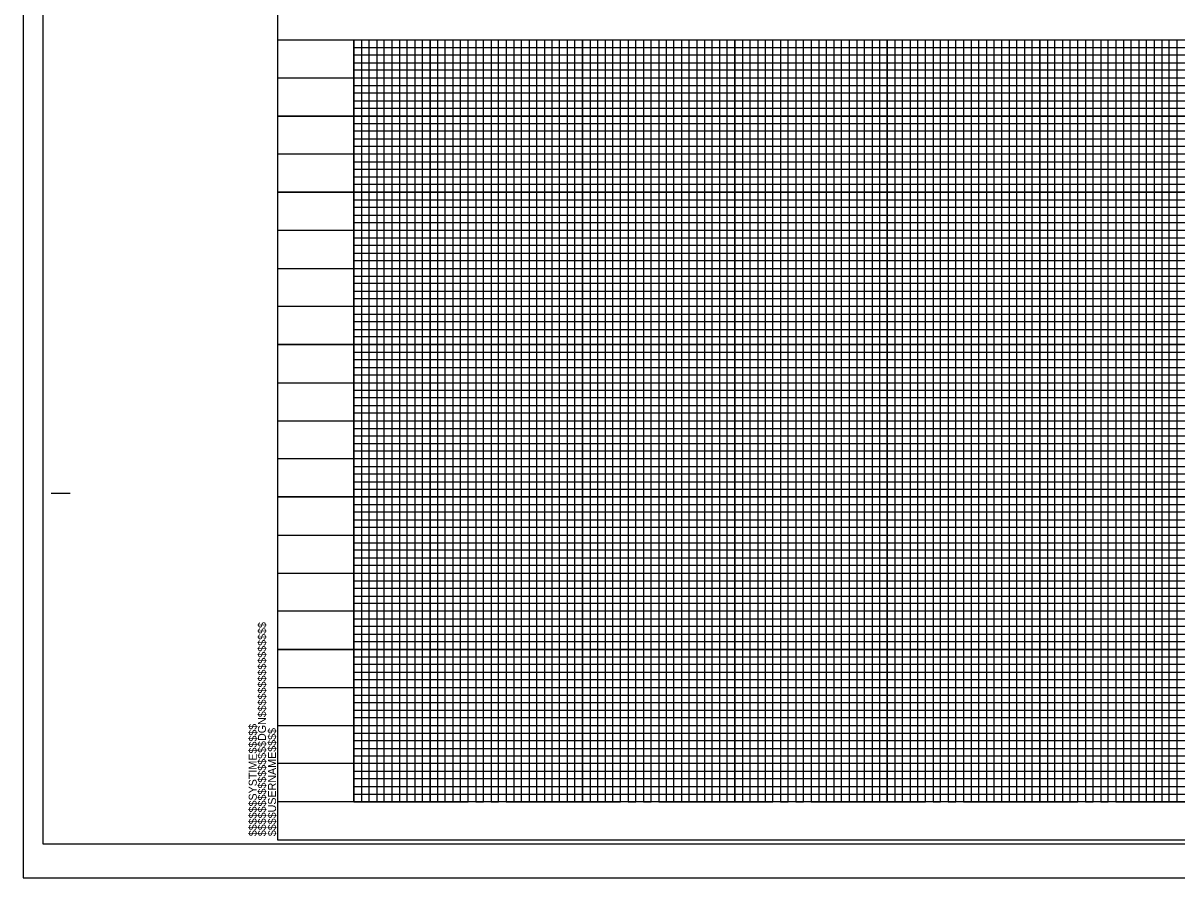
# Model space of a CAD drawing. Extents: x 1648435 to 1651603, y 802691 to 845762.
# Drawn here: x 1648862 to 1649619, y 802691 to 803252 of the extents above; entities that cross this region are included whole.
import ezdxf

# ---------------------------------------------------------------- set-up
doc = ezdxf.new("R2010")
doc.units = 0
for name, color, linetype in [('Sheet Cutting Line CELL', 7, 'Continuous'), ('Sheet DOT Grid CELL', 7, 'Continuous'), ('Sheet Layout Profile Border Port 2', 7, 'Continuous'), ('Sheet Plot Border Inside CELL', 7, 'Continuous'), ('Sheet Plot Border Outside CELL', 7, 'Continuous'), ('Sheet Profile CELL', 7, 'Continuous'), ('Sheet Profile Grid Major CELL', 7, 'Continuous'), ('Sheet Profile Grid Middle CELL', 7, 'Continuous'), ('Sheet Profile Grid Minor CELL', 7, 'Continuous')]:
    doc.layers.add(name, color=color, linetype=linetype)

msp = doc.modelspace()

# ---------------------------------------------------------------- linework, layer by layer
at = {"layer": 'Sheet Cutting Line CELL'}
for p, q in [((1648862.28, 803791.02), (1648862.28, 802691.02)), ((1648862.28, 802691.02), (1650546.28, 802691.02))]:
    msp.add_line(p, q, dxfattribs=at)
at = {"layer": 'Sheet DOT Grid CELL'}
for p, q in [((1649029.28, 803241.02), (1650529.17, 803241.02)), ((1649079.28, 803241.02), (1649079.28, 802741.02)), ((1649129.28, 803241.02), (1649129.28, 802741.02)), ((1649179.28, 803241.02), (1649179.28, 802741.02)), ((1649229.28, 803241.02), (1649229.28, 802741.02)), ((1649279.28, 803241.02), (1649279.28, 802741.02)), ((1649329.28, 803241.02), (1649329.28, 802741.02)), ((1649379.28, 803241.02), (1649379.28, 802741.02)), ((1649429.28, 803241.02), (1649429.28, 802741.02)), ((1649479.28, 803241.02), (1649479.28, 802741.02)), ((1649529.28, 803241.02), (1649529.28, 802741.02)), ((1649579.28, 803241.02), (1649579.28, 802741.02)), ((1649029.28, 803191.02), (1650529.17, 803191.02)), ((1649029.28, 803141.02), (1650529.17, 803141.02)), ((1649029.28, 803091.02), (1650529.17, 803091.02)), ((1649029.28, 803041.02), (1650529.17, 803041.02)), ((1649029.28, 802991.02), (1650529.17, 802991.02)), ((1649029.28, 802941.02), (1650529.17, 802941.02)), ((1649029.28, 802891.02), (1650529.17, 802891.02)), ((1649029.28, 802841.02), (1650529.17, 802841.02)), ((1649029.28, 802791.02), (1650529.17, 802791.02))]:
    msp.add_line(p, q, dxfattribs=at)
at = {"layer": 'Sheet Layout Profile Border Port 2'}
msp.add_lwpolyline([(1649079.28, 803241.02), (1650479.28, 803241.02), (1650479.28, 802741.02), (1649079.28, 802741.02)], close=True, dxfattribs=at)
at = {"layer": 'Sheet Plot Border Inside CELL'}
msp.add_lwpolyline([(1648875.28, 802713.47), (1650541.78, 802713.47), (1650541.78, 803768.57), (1648875.28, 803768.57)], close=True, dxfattribs=at)
at = {"layer": 'Sheet Plot Border Outside CELL'}
msp.add_lwpolyline([(1648862.28, 802691.02), (1650546.28, 802691.02), (1650546.28, 803791.02), (1648862.28, 803791.02)], close=True, dxfattribs=at)
at = {"layer": 'Sheet Profile CELL'}
for p, q in [((1649029.28, 803241.02), (1650529.28, 803241.02)), ((1648880.78, 802943.52), (1648893.28, 802943.52)), ((1650529.28, 802741.02), (1649029.28, 802741.02)), ((1649029.28, 802716.02), (1650529.28, 802716.02)), ((1649029.28, 802716.02), (1649029.28, 802716.02)), ((1649029.28, 802716.02), (1649029.28, 802716.02)), ((1649029.28, 802716.02), (1649029.28, 802716.02)), ((1649029.28, 802716.02), (1649029.28, 802716.02)), ((1649029.28, 802716.02), (1649029.28, 802716.02)), ((1649029.28, 802716.02), (1649029.28, 802716.02)), ((1649029.28, 802716.02), (1649029.28, 802716.02))]:
    msp.add_line(p, q, dxfattribs=at)
msp.add_lwpolyline([(1650529.28, 803766.02), (1649029.28, 803766.02), (1649029.28, 802716.02), (1650529.28, 802716.02)], close=True, dxfattribs=at)
msp.add_lwpolyline([(1649066.78, 802716.02), (1649066.78, 802716.02)], dxfattribs=at)
at = {"layer": 'Sheet Profile Grid Major CELL'}
for p, q in [((1649529.28, 803241.02), (1649579.28, 803241.02)), ((1649029.28, 802741.02), (1649029.28, 802741.02))]:
    msp.add_line(p, q, dxfattribs=at)
for points in [[(1649079.28, 803241.02), (1649079.28, 802741.02), (1649129.28, 802741.02), (1649129.28, 803241.02), (1649179.28, 803241.02), (1649179.28, 802741.02), (1649229.28, 802741.02), (1649229.28, 803241.02), (1649279.28, 803241.02), (1649279.28, 802741.02), (1649329.28, 802741.02), (1649329.28, 803241.02), (1649379.28, 803241.02), (1649379.28, 802741.02), (1649429.28, 802741.02), (1649429.28, 803241.02), (1649479.28, 803241.02), (1649479.28, 802741.02), (1649529.28, 802741.02), (1649529.28, 803241.02), (1649579.28, 803241.02), (1649579.28, 802741.02), (1649629.28, 802741.02)], [(1650529.28, 803191.02), (1649029.28, 803191.02)], [(1650529.28, 803141.02), (1649029.28, 803141.02), (1649029.28, 803091.02), (1650529.28, 803091.02)], [(1650529.28, 803041.02), (1649029.28, 803041.02), (1649029.28, 802991.02), (1650529.28, 802991.02)], [(1650529.28, 802941.02), (1649029.28, 802941.02), (1649029.28, 802891.02), (1650529.28, 802891.02)], [(1650529.28, 802841.02), (1649029.28, 802841.02), (1649029.28, 802841.02), (1649029.28, 802791.02), (1650529.28, 802791.02)], [(1650529.28, 802741.02), (1649029.28, 802741.02)]]:
    msp.add_lwpolyline(points, dxfattribs=at)
at = {"layer": 'Sheet Profile Grid Middle CELL'}
for points in [[(1649054.28, 803241.02), (1649104.28, 803241.02), (1649104.28, 802741.02), (1649154.28, 802741.02), (1649154.28, 803241.02), (1649204.28, 803241.02), (1649204.28, 802741.02), (1649254.28, 802741.02), (1649254.28, 803241.02), (1649304.28, 803241.02), (1649304.28, 802741.02), (1649354.28, 802741.02), (1649354.28, 803241.02), (1649404.28, 803241.02), (1649404.28, 802741.02), (1649454.28, 802741.02), (1649454.28, 803241.02), (1649504.28, 803241.02), (1649504.28, 802741.02), (1649554.28, 802741.02), (1649554.28, 803241.02), (1649604.28, 803241.02), (1649604.28, 802741.02), (1649654.28, 802741.02)], [(1649029.28, 803216.02), (1650529.28, 803216.02)], [(1650529.28, 803166.02), (1649029.28, 803166.02), (1649029.28, 803116.02), (1650529.28, 803116.02)], [(1650529.28, 803066.02), (1649029.28, 803066.02), (1649029.28, 803016.02), (1650529.28, 803016.02)], [(1650529.28, 802966.02), (1649029.28, 802966.02), (1649029.28, 802916.02), (1650529.28, 802916.02)], [(1650529.28, 802866.02), (1649029.28, 802866.02), (1649029.28, 802816.02), (1650529.28, 802816.02)], [(1650529.28, 802766.02), (1649029.28, 802766.02)]]:
    msp.add_lwpolyline(points, dxfattribs=at)
at = {"layer": 'Sheet Profile Grid Minor CELL'}
for p, q in [((1649079.28, 803236.02), (1650479.28, 803236.02)), ((1650479.28, 803231.02), (1649079.28, 803231.02)), ((1649079.28, 803226.02), (1650479.28, 803226.02)), ((1650479.28, 803221.02), (1649079.28, 803221.02)), ((1649079.28, 803211.02), (1650479.28, 803211.02)), ((1650479.28, 803206.02), (1649079.28, 803206.02)), ((1649079.28, 803201.02), (1650479.28, 803201.02)), ((1650479.28, 803196.02), (1649079.28, 803196.02)), ((1649079.28, 803186.02), (1650479.28, 803186.02)), ((1650479.28, 803181.02), (1649079.28, 803181.02)), ((1649079.28, 803176.02), (1650479.28, 803176.02)), ((1650479.28, 803171.02), (1649079.28, 803171.02)), ((1649079.28, 803161.02), (1650479.28, 803161.02)), ((1650479.28, 803156.02), (1649079.28, 803156.02)), ((1649079.28, 803151.02), (1650479.28, 803151.02)), ((1650479.28, 803146.02), (1649079.28, 803146.02)), ((1649079.28, 803136.02), (1650479.28, 803136.02)), ((1650479.28, 803131.02), (1649079.28, 803131.02)), ((1649079.28, 803126.02), (1650479.28, 803126.02)), ((1650479.28, 803121.02), (1649079.28, 803121.02)), ((1649079.28, 803111.02), (1650479.28, 803111.02)), ((1650479.28, 803106.02), (1649079.28, 803106.02)), ((1649079.28, 803101.02), (1650479.28, 803101.02)), ((1650479.28, 803096.02), (1649079.28, 803096.02)), ((1649079.28, 803086.02), (1650479.28, 803086.02)), ((1650479.28, 803081.02), (1649079.28, 803081.02)), ((1649079.28, 803076.02), (1650479.28, 803076.02)), ((1650479.28, 803071.02), (1649079.28, 803071.02)), ((1649079.28, 803061.02), (1650479.28, 803061.02)), ((1650479.28, 803056.02), (1649079.28, 803056.02)), ((1649079.28, 803051.02), (1650479.28, 803051.02)), ((1650479.28, 803046.02), (1649079.28, 803046.17)), ((1649079.28, 803036.02), (1650479.28, 803036.02)), ((1650479.28, 803031.02), (1649079.28, 803031.02)), ((1649079.28, 803026.02), (1650479.28, 803026.02)), ((1650479.28, 803021.02), (1649079.28, 803021.02)), ((1649079.28, 803011.02), (1650479.28, 803011.02)), ((1650479.28, 803006.02), (1649079.28, 803006.02)), ((1649079.28, 803001.02), (1650479.28, 803001.02)), ((1650479.28, 802996.02), (1649079.28, 802996.02)), ((1649079.28, 802986.02), (1650479.28, 802986.02)), ((1650479.28, 802981.02), (1649079.28, 802981.02)), ((1649079.28, 802976.02), (1650479.28, 802976.02)), ((1650479.28, 802971.02), (1649079.28, 802971.02)), ((1649079.28, 802961.02), (1650479.28, 802961.02)), ((1650479.28, 802956.02), (1649079.28, 802956.02)), ((1649079.28, 802951.02), (1650479.28, 802951.02)), ((1650479.28, 802946.02), (1649079.28, 802946.02)), ((1649079.28, 802936.02), (1650479.28, 802936.02)), ((1650479.28, 802931.02), (1649079.28, 802931.02)), ((1649079.28, 802926.02), (1650479.28, 802926.02)), ((1650479.28, 802921.02), (1649079.28, 802921.02)), ((1649079.28, 802911.02), (1650479.28, 802911.02)), ((1650479.28, 802906.02), (1649079.28, 802906.02)), ((1649079.28, 802901.02), (1650479.28, 802901.02)), ((1650479.28, 802896.02), (1649079.28, 802896.02)), ((1649079.28, 802886.02), (1650479.28, 802886.02)), ((1650479.28, 802881.02), (1649079.28, 802881.02)), ((1649079.28, 802876.02), (1650479.28, 802876.02)), ((1650479.28, 802871.02), (1649079.28, 802871.02)), ((1649079.28, 802861.02), (1650479.28, 802861.02)), ((1650479.28, 802856.02), (1649079.28, 802856.02)), ((1649079.28, 802851.02), (1650479.28, 802851.02)), ((1650479.28, 802846.02), (1649079.28, 802846.02)), ((1649079.28, 802836.02), (1650479.28, 802836.02)), ((1650479.28, 802831.02), (1649079.28, 802831.02)), ((1649079.28, 802826.02), (1650479.28, 802826.02)), ((1650479.28, 802821.02), (1649079.28, 802821.02)), ((1649079.28, 802811.02), (1650479.28, 802811.02)), ((1650479.28, 802806.02), (1649079.28, 802806.02)), ((1649079.28, 802801.02), (1650479.28, 802801.02)), ((1650479.28, 802796.02), (1649079.28, 802796.02)), ((1649079.28, 802786.02), (1650479.28, 802786.02)), ((1650479.28, 802781.02), (1649079.28, 802781.02)), ((1649079.28, 802776.02), (1650479.28, 802776.02)), ((1650479.28, 802771.02), (1649079.28, 802771.02)), ((1649079.28, 802761.02), (1650479.28, 802761.02)), ((1650479.28, 802756.02), (1649079.28, 802756.02)), ((1649079.28, 802751.02), (1650479.28, 802751.02)), ((1649079.28, 802746.02), (1650479.28, 802746.02))]:
    msp.add_line(p, q, dxfattribs=at)
for points in [[(1649079.28, 803241.02), (1649084.28, 803241.02), (1649084.28, 802741.02), (1649089.28, 802741.02), (1649089.28, 803241.02), (1649094.28, 803241.02), (1649094.28, 802741.02), (1649099.28, 802741.02), (1649099.28, 803241.02), (1649109.28, 803241.02), (1649109.28, 802741.02), (1649114.28, 802741.02), (1649114.28, 803241.02), (1649119.28, 803241.02), (1649119.28, 802741.02), (1649124.28, 802741.02), (1649134.28, 802741.02), (1649139.28, 802741.02), (1649139.28, 803241.02), (1649144.28, 803241.02), (1649144.28, 802741.02), (1649149.28, 802741.02), (1649149.28, 803241.02), (1649159.28, 803241.02), (1649159.28, 802741.02), (1649164.28, 802741.02), (1649164.28, 803241.02), (1649169.28, 803241.02), (1649169.28, 802741.02), (1649174.28, 802741.02), (1649174.28, 803241.02), (1649184.28, 803241.02), (1649184.28, 802741.02), (1649189.28, 802741.02), (1649189.28, 803241.02), (1649194.28, 803241.02), (1649194.28, 802741.02), (1649199.28, 802741.02), (1649199.28, 803241.02), (1649209.28, 803241.02), (1649209.28, 802741.02), (1649214.28, 802741.02), (1649214.28, 803241.02), (1649219.28, 803241.02), (1649219.28, 802741.02), (1649224.28, 802741.02), (1649224.28, 803241.02), (1649234.28, 803241.02), (1649234.28, 802741.02), (1649239.28, 802741.02), (1649239.28, 803241.02), (1649244.28, 803241.02), (1649244.28, 802741.02), (1649249.28, 802741.02), (1649249.28, 803241.02), (1649259.28, 803241.02), (1649259.28, 802741.02), (1649264.28, 802741.02), (1649264.28, 803241.02), (1649269.28, 803241.02), (1649269.28, 802741.02), (1649274.28, 802741.02), (1649274.28, 803241.02), (1649284.28, 803241.02), (1649284.28, 802741.02), (1649289.28, 802741.02), (1649289.28, 803241.02), (1649294.28, 803241.02), (1649294.28, 802741.02)], [(1649124.28, 802741.02), (1649124.28, 803241.02), (1649134.28, 803241.02), (1649134.28, 802741.02)], [(1649294.28, 802741.02), (1649299.28, 802741.02), (1649299.28, 803241.02), (1649309.28, 803241.02), (1649309.28, 802741.02), (1649314.28, 802741.02), (1649314.28, 803241.02), (1649319.28, 803241.02), (1649319.28, 802741.02), (1649324.28, 802741.02), (1649324.28, 803241.02), (1649334.28, 803241.02), (1649334.28, 802741.02), (1649339.28, 802741.02), (1649339.28, 803241.02), (1649344.28, 803241.02), (1649344.28, 802741.02), (1649349.28, 802741.02), (1649349.28, 803241.02), (1649359.28, 803241.02), (1649359.28, 802741.02), (1649364.28, 802741.02), (1649364.28, 803241.02), (1649369.28, 803241.02), (1649369.28, 802741.02), (1649374.28, 802741.02), (1649374.28, 803241.02), (1649384.28, 803241.02), (1649384.28, 802741.02), (1649389.28, 802741.02), (1649389.28, 803241.02), (1649394.28, 803241.02), (1649394.28, 802741.02), (1649399.28, 802741.02), (1649399.28, 803241.02), (1649409.28, 803241.02), (1649409.28, 802741.02), (1649414.28, 802741.02), (1649414.28, 803241.02), (1649419.28, 803241.02), (1649419.28, 802741.02), (1649424.28, 802741.02), (1649424.28, 803241.02), (1649434.28, 803241.02), (1649434.28, 802741.02), (1649439.28, 802741.02), (1649439.28, 803241.02), (1649444.28, 803241.02), (1649444.28, 802741.02), (1649449.28, 802741.02), (1649449.28, 803241.02), (1649459.28, 803241.02), (1649459.28, 802741.02), (1649464.28, 802741.02), (1649464.28, 803241.02), (1649469.28, 803241.02), (1649469.28, 802741.02), (1649474.28, 802741.02), (1649474.28, 803241.02), (1649484.28, 803241.02), (1649484.28, 802741.02), (1649489.28, 802741.02), (1649489.28, 803241.02), (1649494.28, 803241.02), (1649494.28, 802741.02), (1649499.28, 802741.02), (1649499.28, 803241.02), (1649509.28, 803241.02), (1649509.28, 802741.02), (1649514.28, 802741.02), (1649514.28, 803241.02), (1649519.28, 803241.02), (1649519.28, 802741.02), (1649524.28, 802741.02), (1649524.28, 803241.02), (1649534.28, 803241.02), (1649534.28, 802741.02), (1649539.28, 802741.02), (1649539.28, 803241.02), (1649544.28, 803241.02), (1649544.28, 802741.02), (1649549.28, 802741.02), (1649549.28, 803241.02), (1649559.28, 803241.02), (1649559.28, 802741.02), (1649564.28, 802741.02), (1649564.28, 803241.02), (1649569.28, 803241.02), (1649569.28, 802741.02), (1649574.28, 802741.02), (1649574.28, 803241.02), (1649584.28, 803241.02), (1649584.28, 802741.02), (1649589.28, 802741.02), (1649589.28, 803241.02), (1649594.28, 803241.02), (1649594.28, 802741.02), (1649599.28, 802741.02), (1649599.28, 803241.02), (1649609.28, 803241.02)], [(1649609.28, 803241.02), (1649609.28, 802741.02), (1649614.28, 802741.02), (1649614.28, 803241.02), (1649619.28, 803241.02), (1649619.28, 802741.02), (1649624.28, 802741.02)]]:
    msp.add_lwpolyline(points, dxfattribs=at)

# ---------------------------------------------------------------- texts
at = {"layer": 'Sheet Profile CELL'}
for s, p in [('$$$$$$$$$$$$$$$$DGN$$$$$$$$$$$$$$$$', (1649021.64, 802718.4)), ('$$$$$$SYSTIME$$$$$', (1649015.59, 802718.4)), ('$$$$USERNAME$$$$', (1649028.22, 802718.41))]:
    msp.add_text(s, height=5.25, rotation=90, dxfattribs=at).set_placement(p)

doc.saveas('drawing.dxf')
